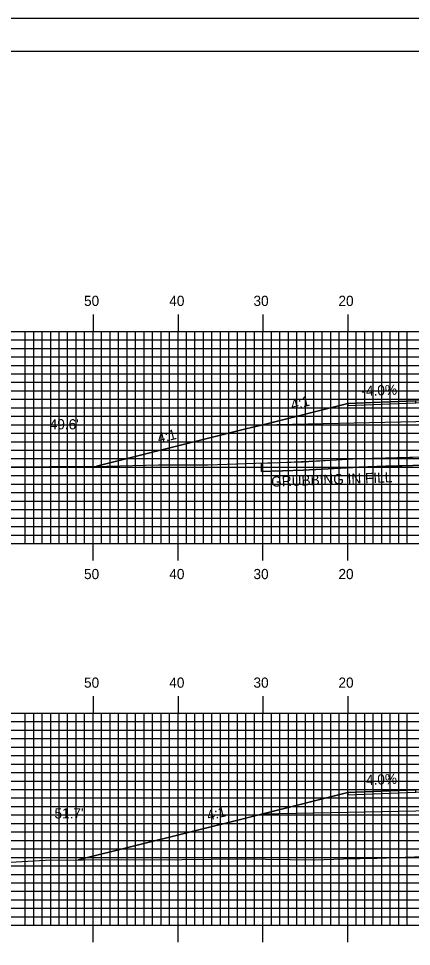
# Model space of a CAD drawing. Extents: x 1777531 to 1777875, y 442591 to 442811.
# Drawn here: x 1777638.5 to 1777684.8, y 442701.2 to 442810.5 of the extents above; entities that cross this region are included whole.
import ezdxf

# ---------------------------------------------------------------- set-up
doc = ezdxf.new("R2010")
doc.units = 0
for name, color, linetype in [('ANNOTATION', 7, 'Continuous'), ('BORDER', 7, 'Continuous'), ('D_Roadway_Centerline', 7, 'Continuous'), ('D_Roadway_Edge_Shoulder', 7, 'Continuous'), ('D_Roadway_SlopeLines', 7, 'Continuous'), ('D_Roadway_SubGrade', 7, 'Continuous'), ('D_Text_Standard', 7, 'Continuous'), ('GRUBBING IN FILL', 7, 'Continuous'), ('H_V ANNOTATION', 7, 'Continuous'), ('MAJOR', 7, 'Continuous'), ('MINOR', 7, 'Continuous'), ('PLOT BOUNDARY', 7, 'Continuous'), ('S_Roadway_Centerline', 7, 'Continuous')]:
    doc.layers.add(name, color=color, linetype=linetype)

msp = doc.modelspace()

# ---------------------------------------------------------------- linework, layer by layer
at = {"layer": 'BORDER'}
msp.add_lwpolyline([(1777547.68, 442596.67), (1777867.68, 442596.67), (1777867.68, 442806.67), (1777547.68, 442806.67)], close=True, dxfattribs=at)
at = {"layer": 'D_Roadway_Centerline'}
for points in [[(1777647.68, 442757.78), (1777665.28, 442762.18), (1777666.08, 442762.38), (1777667.1, 442762.63), (1777677.28, 442765.18), (1777680.02, 442765.29), (1777685.28, 442765.5), (1777697.28, 442765.74), (1777698.56, 442765.71), (1777709.28, 442765.5), (1777713.52, 442765.33), (1777717.28, 442765.18), (1777727.45, 442762.63), (1777740.8, 442759.3)], [(1777645.53, 442711.37), (1777665.28, 442716.3), (1777665.54, 442716.37), (1777667.1, 442716.76), (1777677.28, 442719.3), (1777680.25, 442719.42), (1777685.28, 442719.62), (1777690.81, 442719.73), (1777697.28, 442719.86), (1777697.28, 442719.86), (1777709.28, 442719.62), (1777717.28, 442719.3), (1777727.45, 442716.76), (1777740.11, 442713.59), (1777740.11, 442713.59)]]:
    msp.add_lwpolyline(points, dxfattribs=at)
at = {"layer": 'D_Roadway_Edge_Shoulder'}
for points in [[(1777685.28, 442765.5), (1777677.28, 442765.18), (1777677.28, 442764.93), (1777685.28, 442765.25)], [(1777685.28, 442719.62), (1777677.28, 442719.3), (1777677.28, 442719.05), (1777685.28, 442719.37)]]:
    msp.add_lwpolyline(points, close=True, dxfattribs=at)
at = {"layer": 'D_Roadway_SlopeLines'}
for points in [[(1777677.28, 442765.18), (1777667.1, 442762.63), (1777665.28, 442762.18), (1777647.68, 442757.78)], [(1777677.28, 442719.3), (1777667.1, 442716.76), (1777665.28, 442716.3), (1777645.53, 442711.37)]]:
    msp.add_lwpolyline(points, dxfattribs=at)
at = {"layer": 'D_Roadway_SubGrade'}
for points in [[(1777685.28, 442763), (1777667.1, 442762.63), (1777677.28, 442765.18), (1777677.28, 442764.93), (1777685.28, 442765.25), (1777697.28, 442765.49), (1777709.28, 442765.25), (1777717.28, 442764.93), (1777717.28, 442765.18), (1777727.45, 442762.63), (1777709.28, 442763), (1777697.28, 442763.24)], [(1777685.28, 442717.12), (1777667.1, 442716.76), (1777677.28, 442719.3), (1777677.28, 442719.05), (1777685.28, 442719.37), (1777697.28, 442719.61), (1777709.28, 442719.37), (1777717.28, 442719.05), (1777717.28, 442719.3), (1777727.45, 442716.76), (1777709.28, 442717.12), (1777697.28, 442717.36)]]:
    msp.add_lwpolyline(points, close=True, dxfattribs=at)
at = {"layer": 'GRUBBING IN FILL'}
msp.add_line((1777667.1, 442758.15), (1777667.1, 442757.15), dxfattribs=at)
msp.add_line((1777667.1, 442758.15), (1777667.1, 442757.15), dxfattribs=at)
msp.add_lwpolyline([(1777667.1, 442758.15), (1777669.22, 442758.21), (1777675.28, 442758.49), (1777678.54, 442758.68), (1777681.74, 442758.77), (1777687.32, 442758.92), (1777692.07, 442758.98), (1777697.28, 442759.01), (1777697.28, 442758.01), (1777694.46, 442757.97), (1777689.7, 442757.99), (1777681.78, 442757.77), (1777678.58, 442757.68), (1777672.07, 442757.3), (1777667.1, 442757.15)], close=True, dxfattribs=at)
msp.add_lwpolyline([(1777667.1, 442758.15), (1777669.22, 442758.21), (1777675.28, 442758.49), (1777678.54, 442758.68), (1777681.74, 442758.77), (1777687.32, 442758.92), (1777692.07, 442758.98), (1777697.28, 442759.01), (1777697.28, 442758.01), (1777694.46, 442757.97), (1777689.7, 442757.99), (1777681.78, 442757.77), (1777678.58, 442757.68), (1777672.07, 442757.3), (1777667.1, 442757.15)], close=True, dxfattribs=at)
msp.add_lwpolyline([(1777667.1, 442757.15), (1777672.07, 442757.3), (1777678.58, 442757.68), (1777684.98, 442757.85), (1777689.7, 442757.99), (1777694.46, 442757.97), (1777707.74, 442758.17), (1777716.86, 442758.27), (1777725.04, 442758.12), (1777727.45, 442758.13)], dxfattribs=at)
msp.add_lwpolyline([(1777667.1, 442757.15), (1777672.07, 442757.3), (1777678.58, 442757.68), (1777684.98, 442757.85), (1777689.7, 442757.99), (1777694.46, 442757.97), (1777707.74, 442758.17), (1777716.86, 442758.27), (1777725.04, 442758.12), (1777727.45, 442758.13)], dxfattribs=at)
at = {"layer": 'MAJOR'}
for p, q in [((1777647.28, 442775.67), (1777647.28, 442773.67)), ((1777657.28, 442775.67), (1777657.28, 442773.67)), ((1777667.28, 442775.67), (1777667.28, 442773.67)), ((1777677.28, 442775.67), (1777677.28, 442773.67)), ((1777557.28, 442773.67), (1777837.28, 442773.67)), ((1777557.28, 442773.67), (1777837.28, 442773.67)), ((1777647.28, 442748.67), (1777647.28, 442773.67)), ((1777657.28, 442748.67), (1777657.28, 442773.67)), ((1777667.28, 442748.67), (1777667.28, 442773.67)), ((1777677.28, 442748.67), (1777677.28, 442773.67)), ((1777557.28, 442768.67), (1777837.28, 442768.67)), ((1777557.28, 442763.67), (1777837.28, 442763.67)), ((1777557.28, 442758.67), (1777837.28, 442758.67)), ((1777557.28, 442753.67), (1777837.28, 442753.67)), ((1777557.28, 442748.67), (1777837.28, 442748.67)), ((1777557.28, 442748.67), (1777837.28, 442748.67)), ((1777647.28, 442746.66), (1777647.28, 442748.67)), ((1777657.28, 442746.66), (1777657.28, 442748.67)), ((1777667.28, 442746.66), (1777667.28, 442748.67)), ((1777677.28, 442746.66), (1777677.28, 442748.67)), ((1777647.28, 442730.67), (1777647.28, 442728.67)), ((1777657.28, 442730.67), (1777657.28, 442728.67)), ((1777667.28, 442730.67), (1777667.28, 442728.67)), ((1777677.28, 442730.67), (1777677.28, 442728.67)), ((1777557.28, 442728.67), (1777837.28, 442728.67)), ((1777557.28, 442728.67), (1777837.28, 442728.67)), ((1777647.28, 442703.67), (1777647.28, 442728.67)), ((1777657.28, 442703.67), (1777657.28, 442728.67)), ((1777667.28, 442703.67), (1777667.28, 442728.67)), ((1777677.28, 442703.67), (1777677.28, 442728.67)), ((1777557.28, 442723.67), (1777837.28, 442723.67)), ((1777557.28, 442718.67), (1777837.28, 442718.67)), ((1777557.28, 442713.67), (1777837.28, 442713.67)), ((1777557.28, 442708.67), (1777837.28, 442708.67)), ((1777557.28, 442703.67), (1777837.28, 442703.67)), ((1777557.28, 442703.67), (1777837.28, 442703.67)), ((1777647.28, 442701.66), (1777647.28, 442703.67)), ((1777657.28, 442701.66), (1777657.28, 442703.67)), ((1777667.28, 442701.66), (1777667.28, 442703.67)), ((1777677.28, 442701.66), (1777677.28, 442703.67))]:
    msp.add_line(p, q, dxfattribs=at)
at = {"layer": 'MINOR'}
for p, q in [((1777639.28, 442748.67), (1777639.28, 442773.67)), ((1777640.28, 442748.67), (1777640.28, 442773.67)), ((1777641.28, 442748.67), (1777641.28, 442773.67)), ((1777642.28, 442748.67), (1777642.28, 442773.67)), ((1777643.28, 442748.67), (1777643.28, 442773.67)), ((1777644.28, 442748.67), (1777644.28, 442773.67)), ((1777645.28, 442748.67), (1777645.28, 442773.67)), ((1777646.28, 442748.67), (1777646.28, 442773.67)), ((1777648.28, 442748.67), (1777648.28, 442773.67)), ((1777649.28, 442748.67), (1777649.28, 442773.67)), ((1777650.28, 442748.67), (1777650.28, 442773.67)), ((1777651.28, 442748.67), (1777651.28, 442773.67)), ((1777652.28, 442748.67), (1777652.28, 442773.67)), ((1777653.28, 442748.67), (1777653.28, 442773.67)), ((1777654.28, 442748.67), (1777654.28, 442773.67)), ((1777655.28, 442748.67), (1777655.28, 442773.67)), ((1777656.28, 442748.67), (1777656.28, 442773.67)), ((1777658.28, 442748.67), (1777658.28, 442773.67)), ((1777659.28, 442748.67), (1777659.28, 442773.67)), ((1777660.28, 442748.67), (1777660.28, 442773.67)), ((1777661.28, 442748.67), (1777661.28, 442773.67)), ((1777662.28, 442748.67), (1777662.28, 442773.67)), ((1777663.28, 442748.67), (1777663.28, 442773.67)), ((1777664.28, 442748.67), (1777664.28, 442773.67)), ((1777665.28, 442748.67), (1777665.28, 442773.67)), ((1777666.28, 442748.67), (1777666.28, 442773.67)), ((1777668.28, 442748.67), (1777668.28, 442773.67)), ((1777669.28, 442748.67), (1777669.28, 442773.67)), ((1777670.28, 442748.67), (1777670.28, 442773.67)), ((1777671.28, 442748.67), (1777671.28, 442773.67)), ((1777672.28, 442748.67), (1777672.28, 442773.67)), ((1777673.28, 442748.67), (1777673.28, 442773.67)), ((1777674.28, 442748.67), (1777674.28, 442773.67)), ((1777675.28, 442748.67), (1777675.28, 442773.67)), ((1777676.28, 442748.67), (1777676.28, 442773.67)), ((1777678.28, 442748.67), (1777678.28, 442773.67)), ((1777679.28, 442748.67), (1777679.28, 442773.67)), ((1777680.28, 442748.67), (1777680.28, 442773.67)), ((1777681.28, 442748.67), (1777681.28, 442773.67)), ((1777682.28, 442748.67), (1777682.28, 442773.67)), ((1777683.28, 442748.67), (1777683.28, 442773.67)), ((1777684.28, 442748.67), (1777684.28, 442773.67)), ((1777557.28, 442772.67), (1777837.28, 442772.67)), ((1777557.28, 442771.67), (1777837.28, 442771.67)), ((1777557.28, 442770.67), (1777837.28, 442770.67)), ((1777557.28, 442769.67), (1777837.28, 442769.67)), ((1777557.28, 442767.67), (1777837.28, 442767.67)), ((1777557.28, 442766.67), (1777837.28, 442766.67)), ((1777557.28, 442765.67), (1777837.28, 442765.67)), ((1777557.28, 442764.67), (1777837.28, 442764.67)), ((1777557.28, 442762.67), (1777837.28, 442762.67)), ((1777557.28, 442761.67), (1777837.28, 442761.67)), ((1777557.28, 442760.67), (1777837.28, 442760.67)), ((1777557.28, 442759.67), (1777837.28, 442759.67)), ((1777557.28, 442757.67), (1777837.28, 442757.67)), ((1777557.28, 442756.67), (1777837.28, 442756.67)), ((1777557.28, 442755.67), (1777837.28, 442755.67)), ((1777557.28, 442754.67), (1777837.28, 442754.67)), ((1777557.28, 442752.67), (1777837.28, 442752.67)), ((1777557.28, 442751.67), (1777837.28, 442751.67)), ((1777557.28, 442750.67), (1777837.28, 442750.67)), ((1777557.28, 442749.67), (1777837.28, 442749.67)), ((1777639.28, 442703.67), (1777639.28, 442728.67)), ((1777640.28, 442703.67), (1777640.28, 442728.67)), ((1777641.28, 442703.67), (1777641.28, 442728.67)), ((1777642.28, 442703.67), (1777642.28, 442728.67)), ((1777643.28, 442703.67), (1777643.28, 442728.67)), ((1777644.28, 442703.67), (1777644.28, 442728.67)), ((1777645.28, 442703.67), (1777645.28, 442728.67)), ((1777646.28, 442703.67), (1777646.28, 442728.67)), ((1777648.28, 442703.67), (1777648.28, 442728.67)), ((1777649.28, 442703.67), (1777649.28, 442728.67)), ((1777650.28, 442703.67), (1777650.28, 442728.67)), ((1777651.28, 442703.67), (1777651.28, 442728.67)), ((1777652.28, 442703.67), (1777652.28, 442728.67)), ((1777653.28, 442703.67), (1777653.28, 442728.67)), ((1777654.28, 442703.67), (1777654.28, 442728.67)), ((1777655.28, 442703.67), (1777655.28, 442728.67)), ((1777656.28, 442703.67), (1777656.28, 442728.67)), ((1777658.28, 442703.67), (1777658.28, 442728.67)), ((1777659.28, 442703.67), (1777659.28, 442728.67)), ((1777660.28, 442703.67), (1777660.28, 442728.67)), ((1777661.28, 442703.67), (1777661.28, 442728.67)), ((1777662.28, 442703.67), (1777662.28, 442728.67)), ((1777663.28, 442703.67), (1777663.28, 442728.67)), ((1777664.28, 442703.67), (1777664.28, 442728.67)), ((1777665.28, 442703.67), (1777665.28, 442728.67)), ((1777666.28, 442703.67), (1777666.28, 442728.67)), ((1777668.28, 442703.67), (1777668.28, 442728.67)), ((1777669.28, 442703.67), (1777669.28, 442728.67)), ((1777670.28, 442703.67), (1777670.28, 442728.67)), ((1777671.28, 442703.67), (1777671.28, 442728.67)), ((1777672.28, 442703.67), (1777672.28, 442728.67)), ((1777673.28, 442703.67), (1777673.28, 442728.67)), ((1777674.28, 442703.67), (1777674.28, 442728.67)), ((1777675.28, 442703.67), (1777675.28, 442728.67)), ((1777676.28, 442703.67), (1777676.28, 442728.67)), ((1777678.28, 442703.67), (1777678.28, 442728.67)), ((1777679.28, 442703.67), (1777679.28, 442728.67)), ((1777680.28, 442703.67), (1777680.28, 442728.67)), ((1777681.28, 442703.67), (1777681.28, 442728.67)), ((1777682.28, 442703.67), (1777682.28, 442728.67)), ((1777683.28, 442703.67), (1777683.28, 442728.67)), ((1777684.28, 442703.67), (1777684.28, 442728.67)), ((1777557.28, 442727.67), (1777837.28, 442727.67)), ((1777557.28, 442726.67), (1777837.28, 442726.67)), ((1777557.28, 442725.67), (1777837.28, 442725.67)), ((1777557.28, 442724.67), (1777837.28, 442724.67)), ((1777557.28, 442722.67), (1777837.28, 442722.67)), ((1777557.28, 442721.67), (1777837.28, 442721.67)), ((1777557.28, 442720.67), (1777837.28, 442720.67)), ((1777557.28, 442719.67), (1777837.28, 442719.67)), ((1777557.28, 442717.67), (1777837.28, 442717.67)), ((1777557.28, 442716.67), (1777837.28, 442716.67)), ((1777557.28, 442715.67), (1777837.28, 442715.67)), ((1777557.28, 442714.67), (1777837.28, 442714.67)), ((1777557.28, 442712.67), (1777837.28, 442712.67)), ((1777557.28, 442711.67), (1777837.28, 442711.67)), ((1777557.28, 442710.67), (1777837.28, 442710.67)), ((1777557.28, 442709.67), (1777837.28, 442709.67)), ((1777557.28, 442707.67), (1777837.28, 442707.67)), ((1777557.28, 442706.67), (1777837.28, 442706.67)), ((1777557.28, 442705.67), (1777837.28, 442705.67)), ((1777557.28, 442704.67), (1777837.28, 442704.67))]:
    msp.add_line(p, q, dxfattribs=at)
at = {"layer": 'PLOT BOUNDARY'}
msp.add_lwpolyline([(1777531.49, 442590.55), (1777871.49, 442590.55), (1777871.49, 442810.55), (1777531.49, 442810.55)], close=True, dxfattribs=at)
at = {"layer": 'S_Roadway_Centerline'}
for points in [[(1777626.02, 442757.69), (1777642.13, 442757.73), (1777648.89, 442757.79), (1777654.97, 442757.95), (1777660.83, 442757.95), (1777666.42, 442758.13), (1777672.02, 442758.3), (1777678.54, 442758.68), (1777684.95, 442758.85), (1777689.69, 442758.99), (1777694.45, 442758.97), (1777707.73, 442759.17), (1777716.86, 442759.27), (1777725.05, 442759.12), (1777732.48, 442759.14), (1777736.36, 442759.18), (1777740.31, 442759.28), (1777747.89, 442759.49), (1777755.31, 442759.67)], [(1777629.31, 442710.62), (1777641.65, 442711.33), (1777650.59, 442711.41), (1777654.25, 442711.39), (1777664.71, 442711.51), (1777673.36, 442711.39), (1777676.76, 442711.51), (1777680.73, 442711.58), (1777697.29, 442712.17), (1777704.26, 442712.3), (1777719.29, 442712.59), (1777727.43, 442712.82), (1777735.4, 442713.28), (1777743.13, 442713.8), (1777747.14, 442714.02), (1777751.12, 442714.04), (1777758.7, 442713.92)]]:
    msp.add_lwpolyline(points, dxfattribs=at)

# ---------------------------------------------------------------- texts
at = {"layer": 'ANNOTATION'}
for s, rotation, p in [('-4.0%', 2.2907, (1777678.91, 442766.04)), ('4:1', 14.0329, (1777670.73, 442764.4)), ('4:1', 14.0346, (1777655.02, 442760.47)), ('-4.0%', 2.2907, (1777678.91, 442720.17)), ('4:1', 14.0329, (1777660.85, 442716))]:
    msp.add_text(s, height=1.2, rotation=rotation, dxfattribs=at).set_placement(p)
at = {"layer": 'D_Text_Standard'}
for s, p in [("49.6'", (1777642.17, 442762.12)), ("51.7'", (1777642.73, 442716.26))]:
    msp.add_text(s, height=1.2, dxfattribs=at).set_placement(p)
at = {"layer": 'GRUBBING IN FILL'}
msp.add_text('GRUBBING IN FILL', height=1.2, rotation=2.1344, dxfattribs=at).set_placement((1777668.28, 442755.36))
at = {"layer": 'H_V ANNOTATION'}
for s, p in [('50', (1777646.21, 442776.67)), ('40', (1777656.25, 442776.67)), ('30', (1777666.17, 442776.67)), ('20', (1777676.18, 442776.67)), ('50', (1777646.21, 442744.47)), ('40', (1777656.25, 442744.47)), ('30', (1777666.17, 442744.47)), ('20', (1777676.18, 442744.47)), ('50', (1777646.21, 442731.67)), ('40', (1777656.25, 442731.67)), ('30', (1777666.17, 442731.67)), ('20', (1777676.18, 442731.67))]:
    msp.add_text(s, height=1.2, dxfattribs=at).set_placement(p)

doc.saveas('drawing.dxf')
